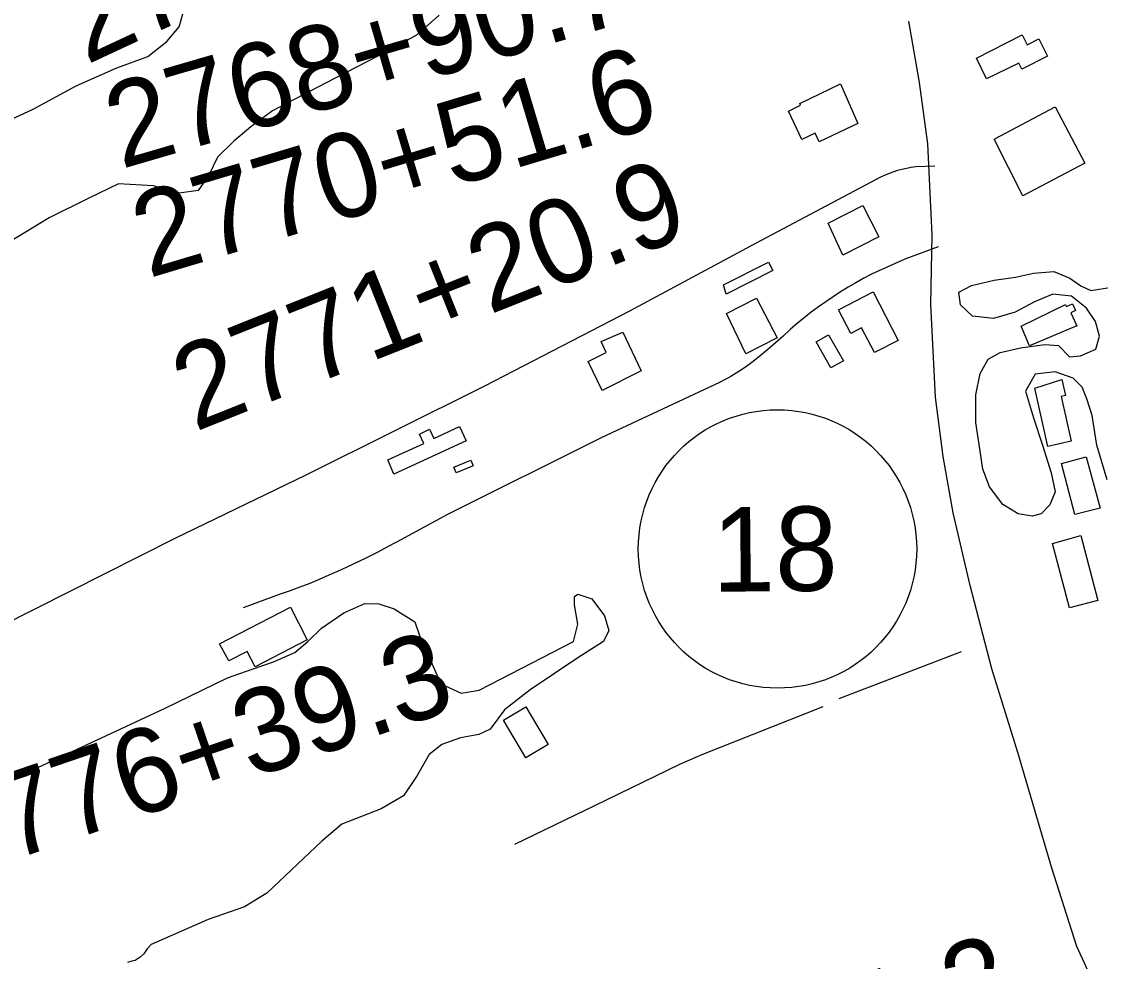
# Model space of a CAD drawing. Extents: x 3567028 to 3605064, y 510945 to 536587.
# Drawn here: x 3573792 to 3575071, y 531241 to 532355 of the extents above; entities that cross this region are included whole.
import ezdxf

# ---------------------------------------------------------------- set-up
doc = ezdxf.new("R2010")
doc.units = 0
for name, color, linetype in [('V-BLDG-OTLN', 7, 'Continuous'), ('V-ROAD-CNTR', 7, 'Continuous'), ('V-ROAD-IDEN', 7, 'Continuous'), ('V-SITE-VEGE', 7, 'Continuous'), ('V-SURV-IDEN', 7, 'Continuous'), ('V-TOPO-SHOR', 7, 'Continuous')]:
    doc.layers.add(name, color=color, linetype=linetype)

msp = doc.modelspace()

# ---------------------------------------------------------------- linework, layer by layer
at = {"layer": 'V-BLDG-OTLN'}
for points in [[(3574923.8, 532311.3), (3574977.9, 532339.1), (3574983.9, 532327.4), (3574997.4, 532334.3), (3575007.7, 532313.9), (3574977.3, 532298.3), (3574973.7, 532305.6), (3574935.6, 532287)], [(3574783.1, 532234), (3574737.3, 532212.1), (3574732.4, 532222.4), (3574716.8, 532215), (3574700.7, 532248.7), (3574715.1, 532255.6), (3574714.1, 532257.7), (3574762.6, 532280.8)], [(3574944.6, 532215.3), (3575017, 532253.6), (3575052.3, 532187.1), (3574978.7, 532148.2)], [(3574747.7, 532115.7), (3574789, 532136.7), (3574807.8, 532099.5), (3574765.1, 532077.8)], [(3574623.7, 532042.6), (3574677.1, 532069.7), (3574682.2, 532059.6), (3574627, 532031.6)], [(3574760.2, 532013.1), (3574801.3, 532034.3), (3574830.9, 531976.9), (3574802.7, 531962.4), (3574787.5, 531991.8), (3574774.9, 531985.2)], [(3574627.4, 532008.7), (3574663.1, 532027.1), (3574687.4, 531980), (3574650.4, 531960.9)], [(3575042.7, 531994.1), (3574986.7, 531970.6), (3574976.5, 531993.8), (3575029.3, 532019.3), (3575030.4, 532017), (3575037.4, 532020.4), (3575041.2, 532012.4), (3575035.4, 532009.6)], [(3575042.7, 531994.1), (3575043, 531994.2), (3575042.7, 531994.1)], [(3574479.9, 531917.7), (3574463.5, 531951.9), (3574484.8, 531962.5), (3574478.8, 531975.7), (3574504.4, 531986.5), (3574526.2, 531941)], [(3574748.2, 531983.5), (3574765.9, 531952.8), (3574751.2, 531944.3), (3574733.5, 531975)], [(3574992.9, 531920.3), (3575024.9, 531930.4), (3575029.1, 531911.5), (3575024.2, 531910.4), (3575035.9, 531857.4), (3575008.2, 531851.3)], [(3574233.1, 531818.5), (3574225.8, 531835.2), (3574268.5, 531854.8), (3574263.3, 531865.9), (3574275.3, 531871.5), (3574280.3, 531860.6), (3574310.9, 531874.7), (3574318.6, 531858)], [(3574327, 531828.3), (3574306.9, 531820.1), (3574304.2, 531826.7), (3574324.3, 531834.9)], [(3575040.2, 531770.4), (3575024.3, 531830.8), (3575053.5, 531839), (3575070.3, 531778.1)], [(3575013.9, 531736.1), (3575047.4, 531745.8), (3575067.6, 531668.8), (3575033.9, 531659.9)], [(3574026.2, 531617.2), (3574110.6, 531660.6), (3574130.4, 531621.9), (3574068.5, 531590.1), (3574059.2, 531608.2), (3574037.5, 531597.1)], [(3574416.1, 531498), (3574389.5, 531482.1), (3574362.9, 531526.7), (3574389.4, 531542.6)]]:
    msp.add_lwpolyline(points, close=True, dxfattribs=at)
at = {"layer": 'V-ROAD-CNTR'}
for points in [[(3575069.6, 531200.2), (3575042.6, 531258.6), (3575013.1, 531351.3), (3574972.8, 531488.5), (3574941.8, 531587.6), (3574916.3, 531686.5), (3574896, 531772.5), (3574884.1, 531839.3), (3574875.1, 531909.6), (3574869.7, 532019.3), (3574871.1, 532102.1), (3574866.1, 532209.7), (3574856.2, 532282.6), (3574843.4, 532355.3)], [(3574874.4, 532183.3), (3574851.7, 532182.5), (3574846.2, 532181.8), (3574840.7, 532180.8), (3574835.2, 532179.6), (3574829.9, 532178.1), (3574824.5, 532176.4), (3574819.3, 532174.5), (3574814.1, 532172.3), (3574809.1, 532169.9), (3574804.1, 532167.3), (3574655.8, 532088.5), (3574512.4, 532011.7), (3574340.7, 531922.5), (3574128.6, 531817.2), (3573973.4, 531742.1), (3573724, 531616.6), (3573508.9, 531503.2), (3573299.5, 531394.5)], [(3574878.1, 532087.6), (3574838.6, 532073.3), (3574799.4, 532055.4), (3574790, 532050.5), (3574780.8, 532045.3), (3574771.7, 532039.9), (3574762.6, 532034.4), (3574753.7, 532028.6), (3574745, 532022.7), (3574736.3, 532016.6), (3574727.8, 532010.2), (3574719.5, 532003.7), (3574711.3, 531997.1), (3574703.2, 531990.2), (3574694.4, 531981.9), (3574685.3, 531973.9), (3574676.2, 531966), (3574666.8, 531958.3), (3574657.3, 531950.8), (3574651.3, 531946.3), (3574645.1, 531942), (3574638.8, 531937.9), (3574632.3, 531934.1), (3574625.7, 531930.4), (3574619, 531927), (3574478.6, 531861.4), (3574296.8, 531770.4), (3574241.2, 531740.5), (3574227.3, 531732.9), (3574213.3, 531725.6), (3574199.1, 531718.5), (3574184.9, 531711.6), (3574170.5, 531704.9), (3574156.1, 531698.5), (3574144.7, 531693.5), (3574133.3, 531688.8), (3574121.8, 531684.3), (3574110.2, 531680), (3574098.5, 531676), (3574054.4, 531660)]]:
    msp.add_lwpolyline(points, dxfattribs=at)
at = {"layer": 'V-ROAD-IDEN'}
msp.add_circle((3574687.8, 531729.7), 165, dxfattribs=at)
at = {"layer": 'V-SITE-VEGE'}
for p, q in [((3573978.6, 532348.7), (3573985.7, 532373.6)), ((3574286.6, 532362.3), (3574259.8, 532338.7)), ((3573963.9, 532331.2), (3573978.6, 532348.7)), ((3573941.5, 532313.2), (3573963.9, 532331.2)), ((3574259.8, 532338.7), (3574226.3, 532320)), ((3574226.3, 532320), (3574152.2, 532281.7)), ((3573904.7, 532299.8), (3573941.5, 532313.2)), ((3573856.3, 532278.5), (3573904.7, 532299.8)), ((3573805.4, 532250.9), (3573856.3, 532278.5)), ((3574152.2, 532281.7), (3574089.1, 532248.9)), ((3573677.1, 532192.7), (3573805.4, 532250.9)), ((3574089.1, 532248.9), (3574063.4, 532230.1)), ((3574063.4, 532230.1), (3574043.4, 532213.1)), ((3574043.4, 532213.1), (3574023.9, 532194.1)), ((3574023.9, 532194.1), (3574013.9, 532172.7)), ((3573906.5, 532162.3), (3573871.6, 532145.5)), ((3573948.3, 532160.2), (3573906.5, 532162.3)), ((3573978.5, 532151.5), (3573948.3, 532160.2)), ((3574013.9, 532172.7), (3574001.1, 532154.6)), ((3574001.1, 532154.6), (3573978.5, 532151.5)), ((3573871.6, 532145.5), (3573824.6, 532122.1)), ((3573824.6, 532122.1), (3573767.8, 532087.9)), ((3574447.3, 531673.4), (3574451, 531676.1)), ((3574451, 531676.1), (3574467.6, 531670.4)), ((3574173.8, 531654.1), (3574198.7, 531665)), ((3574198.7, 531665), (3574215.4, 531664.8)), ((3574215.4, 531664.8), (3574233.4, 531658.6)), ((3574447.2, 531663.5), (3574447.3, 531673.4)), ((3574451.3, 531640.4), (3574447.2, 531663.5)), ((3574467.6, 531670.4), (3574482.6, 531650.3)), ((3574147.3, 531636), (3574173.8, 531654.1)), ((3574233.4, 531658.6), (3574257.9, 531643.4)), ((3574482.6, 531650.3), (3574487.7, 531633.1)), ((3574130.9, 531620.1), (3574147.3, 531636)), ((3574257.9, 531643.4), (3574263.5, 531627.1)), ((3574446, 531620.2), (3574451.3, 531640.4)), ((3574263.5, 531627.1), (3574288.8, 531569.9)), ((3574487.7, 531633.1), (3574481.7, 531620.1)), ((3574115.8, 531606.8), (3574130.9, 531620.1)), ((3574334.2, 531562.4), (3574446, 531620.2)), ((3574481.7, 531620.1), (3574452.5, 531601.6)), ((3574090.4, 531595.9), (3574115.8, 531606.8)), ((3574452.5, 531601.6), (3574394.7, 531562.8)), ((3574036, 531576.9), (3574065, 531587.2)), ((3574065, 531587.2), (3574090.4, 531595.9)), ((3573961.9, 531541), (3574036, 531576.9)), ((3574288.8, 531569.9), (3574313, 531558.7)), ((3574313, 531558.7), (3574334.2, 531562.4)), ((3574394.7, 531562.8), (3574364.1, 531539)), ((3573805.2, 531468.1), (3573961.9, 531541)), ((3574364.1, 531539), (3574347.1, 531516.2)), ((3574333.9, 531509.7), (3574312.2, 531505.9)), ((3574347.1, 531516.2), (3574333.9, 531509.7)), ((3574290, 531498.1), (3574274.9, 531486.2)), ((3574312.2, 531505.9), (3574290, 531498.1)), ((3574274.9, 531486.2), (3574260.6, 531461.2)), ((3573778.3, 531461), (3573805.2, 531468.1)), ((3574260.6, 531461.2), (3574244.4, 531437.1)), ((3574244.4, 531437.1), (3574218, 531421.7)), ((3574218, 531421.7), (3574171.3, 531403.5)), ((3574171.3, 531403.5), (3574147.6, 531383.5)), ((3574147.6, 531383.5), (3574082.6, 531321.8)), ((3574082.6, 531321.8), (3574056.2, 531305.6)), ((3574056.2, 531305.6), (3574013.1, 531290.4)), ((3574013.1, 531290.4), (3573945.5, 531260.8)), ((3573940.7, 531255.6), (3573936.6, 531249.8)), ((3573945.5, 531260.8), (3573940.7, 531255.6)), ((3573922.5, 531241.3), (3573917.2, 531239.6)), ((3573926.5, 531241.8), (3573922.5, 531241.3)), ((3573932.4, 531245.8), (3573926.5, 531241.8)), ((3573936.6, 531249.8), (3573932.4, 531245.8))]:
    msp.add_line(p, q, dxfattribs=at)
msp.add_lwpolyline([(3575078.4, 531811.7), (3575066.4, 531852.9), (3575060.7, 531887.7), (3575054.6, 531907.7), (3575049, 531921.3), (3575038.3, 531932.3), (3575016.8, 531939.8), (3574993.3, 531937), (3574981.7, 531916.9), (3574991.2, 531885.2), (3575001.9, 531852.6), (3575012.3, 531819.9), (3575016.9, 531797.3), (3575010.8, 531782.1), (3575000.3, 531771.4), (3574989.8, 531768.4), (3574973.2, 531771.4), (3574954.9, 531782.5), (3574939, 531803.5), (3574931.2, 531824.3), (3574927.5, 531848.3), (3574923, 531879.5), (3574923, 531912.4), (3574927.9, 531937.6), (3574937.7, 531954.5), (3574951.8, 531962.4), (3574975.7, 531967.9), (3575004.7, 531972), (3575020.9, 531970.9), (3575033.8, 531957.6), (3575046.9, 531958.7), (3575065, 531966.6), (3575069.3, 531981.8), (3575064.6, 531999.1), (3575054, 532015), (3575036.2, 532029.2), (3575014.1, 532031.8), (3574992.4, 532022.7), (3574969.6, 532010.4), (3574943.8, 532002.7), (3574919.1, 532005.8), (3574904.8, 532019.1), (3574902.8, 532034), (3574917.8, 532041.9), (3574944.5, 532048.2), (3574969.8, 532051.9), (3574991.1, 532056.5), (3575015.5, 532058.4), (3575034.3, 532050.5), (3575047.2, 532041.7), (3575059.3, 532036.1), (3575084.2, 532039.8)], dxfattribs=at)
at = {"layer": 'V-TOPO-SHOR'}
msp.add_line((3574905.4, 531607.9), (3574760.7, 531552.2), dxfattribs=at)
msp.add_lwpolyline([(3574741.4, 531542.7), (3574598.9, 531485.9), (3574571.7, 531474.1), (3574470.8, 531425.3), (3574375.9, 531379.3)], dxfattribs=at)

# ---------------------------------------------------------------- texts
at = {"layer": 'V-ROAD-IDEN'}
msp.add_text('18', height=100, rotation=0.555, dxfattribs=at).set_placement((3574610.8, 531678.9))
at = {"layer": 'V-SURV-IDEN'}
for s, rotation, p in [('2766+01.8', 24.9667, (3573868.6, 532303.2)), ('2768+90.7', 16.2533, (3573909.7, 532179.8)), ('2770+51.6', 16.6644, (3573942.2, 532050.4)), ('2771+20.9', 21.706, (3573997.2, 531868.2)), ('2776+39.3', 18.9021, (3573708.4, 531335.5)), ('2781+91.2', 17.6573, (3574367.7, 530987.7))]:
    msp.add_text(s, height=100, rotation=rotation, dxfattribs=at).set_placement(p)

doc.saveas('drawing.dxf')
